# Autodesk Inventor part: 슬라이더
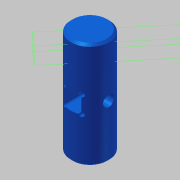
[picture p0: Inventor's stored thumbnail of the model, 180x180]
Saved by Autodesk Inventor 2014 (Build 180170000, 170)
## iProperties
Company: 한국ATC센터
Created: 2015-04
Part Number: 슬라이더
Document SubType Name: Modeling
Designer: KYOUNG IL JANG
Density: 7.85 g/cm^3
Material: 강
Mass: 88.0217 g
Surface Area: 38.9014 cm^2
Volume: 11.213 cm^3
Appearance: 청록색
Author: KYOUNG IL JANG
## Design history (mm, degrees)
sketch "스케치1"
  geometry: C1 r 9 at (0, 0); 1 further point
  constraints: 1 centre point, 1 coincident
  dimensions: "d0" = 18 diameter of C1
extrude "돌출1" new body sketch "스케치1" stored distance "d1" = 50; taper "d2" = 0 deg
node "작업 평면1"
sketch "스케치3"
  geometry: L1 (4, 25)-(-4, 25); L2 (-4, 25)-(-4, -25); L3 (-4, -25)-(4, -25); L4 (4, -25)-(4, 25); 3 further points
  constraints: 8 end point, 2 midpoint, 2 parallel, 1 horizontal, 1 horizontal alignment, 1 perpendicular, 1 vertical alignment
  dimensions: "d5" = 8 distance of L1.start L1.end; "d6" = 50 distance of L1.end L2.end
extrude "돌출3" cut sketch "스케치3" stored distance "d7" = 8; taper "d8" = 0 deg
sketch "스케치4"
  geometry: 5 further points
hole "구멍1" sketch "스케치4" at (4, 4), (-4, 4), (-4, -4), (4, -4) diameter "d9" = 2; stored, may be unused: countersink angle "d13" = 90 deg, drill point angle "d15" = 118 deg; dims "d10" = 6, "d11" = 4, "d12" = 2, "d14" = 8
node "작업 평면2"
sketch "스케치5"
  geometry: 1 further point
hole "구멍2" sketch "스케치5" at (0, 0) diameter "d16" = 5; stored, may be unused: countersink angle "d20" = 90 deg, drill point angle "d22" = 118 deg; dims "d17" = 6, "d18" = 4, "d19" = 2, "d21" = 8
chamfer "모따기1" distance "d23" = 1; stored, may be unused: second distance "d24" = 2, angle "d25" = 45 deg
node "솔리드1"
mirror "대칭1"
